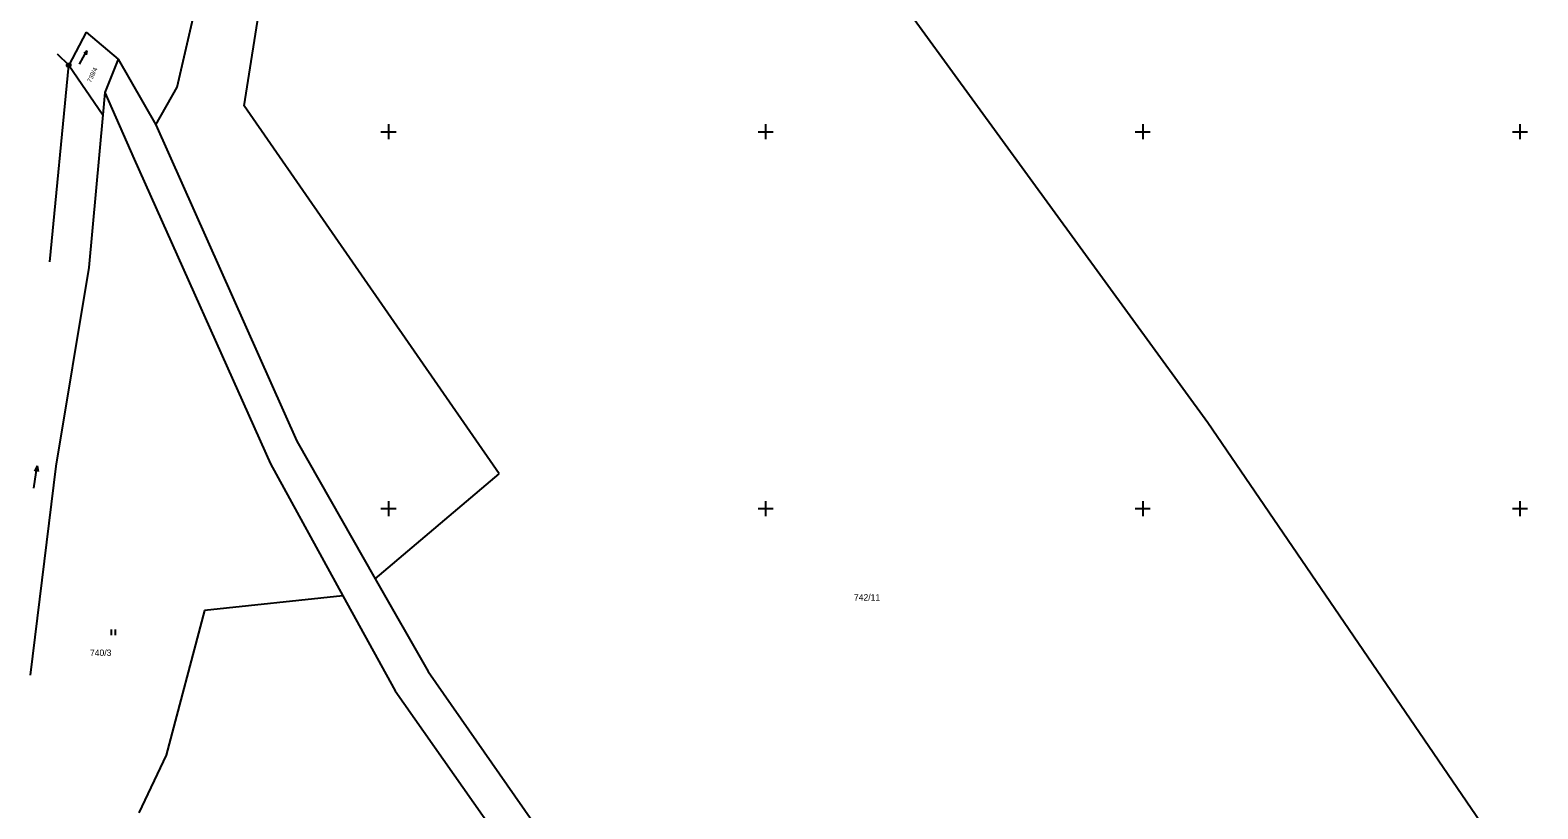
# Model space of a CAD drawing. Extents: x -493648 to -493033, y -1127718 to -1127026.
# Drawn here: x -493647.5 to -493447.6, y -1127439.8 to -1127336.5 of the extents above; entities that cross this region are included whole.
import ezdxf

# ---------------------------------------------------------------- set-up
doc = ezdxf.new("R2010")
doc.units = 0
doc.layers.add('katastrální mapa', color=7, linetype='Continuous')
doc.layers.add('síť', color=7, linetype='Continuous')

msp = doc.modelspace()

# ---------------------------------------------------------------- linework, layer by layer
at = {"layer": 'katastrální mapa'}
for p, q in [((-493628.01, -1127344.09), (-493621.33, -1127315.16)), ((-493491.36, -1127388.6), (-493539.49, -1127322.46)), ((-493619.14, -1127346.56), (-493616.6, -1127330.59)), ((-493640.07, -1127336.77), (-493642.4, -1127341.18)), ((-493640.07, -1127336.77), (-493635.82, -1127340.38)), ((-493640.96, -1127341.02), (-493640, -1127339.26)), ((-493640, -1127339.26), (-493640.39, -1127339.62)), ((-493640, -1127339.26), (-493640.09, -1127339.78)), ((-493644.91, -1127367.26), (-493642.4, -1127341.18)), ((-493643.91, -1127339.64), (-493642.4, -1127341.18)), ((-493642.4, -1127341.18), (-493637.86, -1127347.76)), ((-493635.82, -1127340.38), (-493637.59, -1127344.8)), ((-493635.82, -1127340.38), (-493630.83, -1127349.06)), ((-493637.59, -1127344.8), (-493637.86, -1127347.76)), ((-493637.59, -1127344.8), (-493633.7, -1127353.64)), ((-493630.83, -1127349.06), (-493628.01, -1127344.09)), ((-493585.34, -1127395.37), (-493619.14, -1127346.56)), ((-493637.86, -1127347.76), (-493639.73, -1127368.03)), ((-493630.83, -1127349.06), (-493612.17, -1127391.06)), ((-493633.7, -1127353.64), (-493615.66, -1127394.06)), ((-493639.73, -1127368.03), (-493644.09, -1127394.37)), ((-493447.62, -1127452.73), (-493491.36, -1127388.6)), ((-493612.17, -1127391.06), (-493601.78, -1127409.3)), ((-493644.09, -1127394.37), (-493647.51, -1127422.08)), ((-493647.03, -1127397.27), (-493646.57, -1127394.31)), ((-493646.57, -1127394.31), (-493646.93, -1127395.01)), ((-493646.57, -1127394.31), (-493646.44, -1127395.09)), ((-493615.66, -1127394.06), (-493606.06, -1127411.55)), ((-493601.78, -1127409.3), (-493585.34, -1127395.37)), ((-493601.78, -1127409.3), (-493594.76, -1127421.62)), ((-493606.06, -1127411.55), (-493624.39, -1127413.5)), ((-493606.06, -1127411.55), (-493599.13, -1127424.19)), ((-493624.39, -1127413.5), (-493629.48, -1127432.72)), ((-493636.72, -1127416.78), (-493636.72, -1127416.03)), ((-493636.22, -1127416.03), (-493636.22, -1127416.78)), ((-493594.76, -1127421.62), (-493574.44, -1127450.7)), ((-493599.13, -1127424.19), (-493578.17, -1127454.01)), ((-493629.48, -1127432.72), (-493633.12, -1127440.38))]:
    msp.add_line(p, q, dxfattribs=at)
for radius in [0.25, 0.005]:
    msp.add_circle((-493642.4, -1127341.18), radius, dxfattribs=at)
at = {"layer": 'síť'}
for p, q in [((-493600, -1127349), (-493600, -1127351)), ((-493550, -1127349), (-493550, -1127351)), ((-493500, -1127349), (-493500, -1127351)), ((-493450, -1127349), (-493450, -1127351)), ((-493601, -1127350), (-493599, -1127350)), ((-493551, -1127350), (-493549, -1127350)), ((-493501, -1127350), (-493499, -1127350)), ((-493451, -1127350), (-493449, -1127350)), ((-493600, -1127399), (-493600, -1127401)), ((-493550, -1127399), (-493550, -1127401)), ((-493500, -1127399), (-493500, -1127401)), ((-493450, -1127399), (-493450, -1127401)), ((-493601, -1127400), (-493599, -1127400)), ((-493551, -1127400), (-493549, -1127400)), ((-493501, -1127400), (-493499, -1127400)), ((-493451, -1127400), (-493449, -1127400))]:
    msp.add_line(p, q, dxfattribs=at)

# ---------------------------------------------------------------- texts
at = {"layer": 'katastrální mapa'}
msp.add_text('739/4', height=0.599994, rotation=64.8, dxfattribs=at).set_placement((-493639.45, -1127343.52))
for s, p in [('742/11', (-493538.29, -1127412.2)), ('740/3', (-493639.58, -1127419.55))]:
    msp.add_text(s, height=0.849996, dxfattribs=at).set_placement(p)

doc.saveas('drawing.dxf')
